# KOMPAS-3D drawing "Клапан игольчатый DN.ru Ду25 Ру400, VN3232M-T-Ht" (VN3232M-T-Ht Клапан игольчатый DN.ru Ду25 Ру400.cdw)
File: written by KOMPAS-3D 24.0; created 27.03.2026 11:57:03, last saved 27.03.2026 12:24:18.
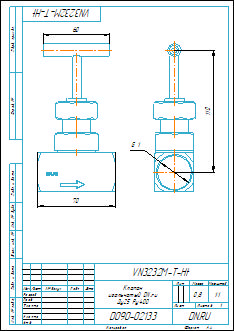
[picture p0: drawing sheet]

Document properties: Автор: Илья; Форматы листов документа: A4; Полное имя файла: VN3232M-T-Ht Клапан игольчатый DN.ru Ду25 Ру400.m3d; Масса: 0.8; Наименование: Клапан игольчатый DN.ru Ду25 Ру400; Количество листов документа: 1; Примечание: D090-02133

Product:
- Body: Body9  | qty 1
    Масса: 0.433192
- Body: Body7  | qty 1
    Масса: 0.81876
- Part/product: Клапан игольчатый DN.ru Ду25 Ру400  | designation VN3232M-T-Ht
    Масса: 0.8
    Раздел спецификации: Прочие изделия
    Примечание: D090-02133

Views: Вид 1, Слева
Referenced files in D:\Обмен\Заказы с фриланса\DN.ru\VNxxM-T-Ht Клапан игольчатый DN.ru Ду8-50 Ру400\VN3232M-T-Ht Клапан игольчатый DN.ru Ду8-50 Ру400\DN8\: VN3232M-T-Ht Клапан игольчатый DN.ru Ду8 Ру400.m3d, VN3232M-T-Ht Клапан игольчатый DN.ru Ду8 Ру400.cdw
Referenced files in D:\Обмен\Заказы с фриланса\DN.ru\VNxxM-T-Ht Клапан игольчатый DN.ru Ду8-50 Ру400\VN3232M-T-Ht Клапан игольчатый DN.ru Ду8-50 Ру400\DN25\: VN3232M-T-Ht Клапан игольчатый DN.ru Ду25 Ру400.m3d
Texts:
  Линейный размер
  VN3232M-T-Ht
  Клапан
  игольчатый DN.ru
  Ду25 Ру400
  Body7
  Клапан игольчатый DN.ru Ду25 Ру400
  VN3232M-T-Ht Клапан игольчатый DN.ru Ду25 Ру400
Dimensions and other numbers on the sheet: 0; 3; 2; 4; 70; 60; 1:1; 1; 0,8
